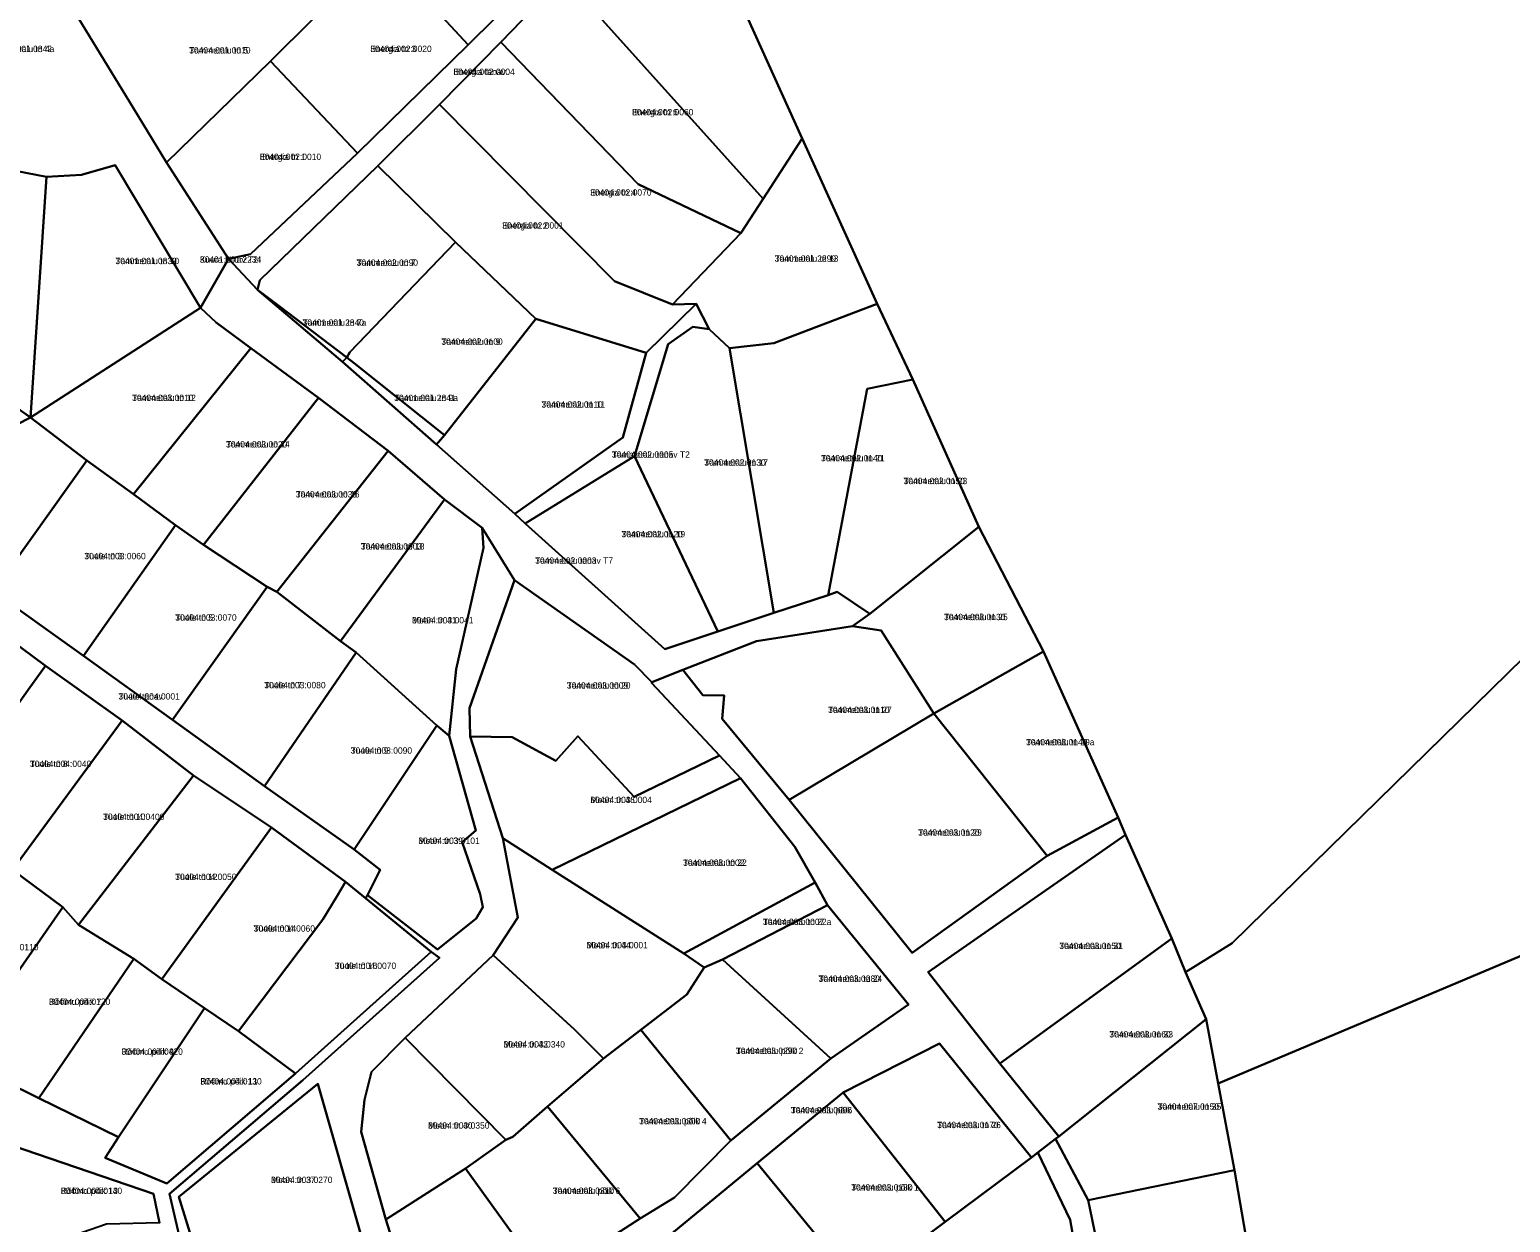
# Model space of a CAD drawing. Extents: x 542681 to 554572, y 6566489 to 6580482.
# Drawn here: x 544171.9 to 544521.7, y 6577252.9 to 6577534.7 of the extents above; entities that cross this region are included whole.
import ezdxf

# ---------------------------------------------------------------- set-up
doc = ezdxf.new("R2010")
doc.units = 0
for name, color, linetype in [('L_AADRESS', 7, 'Continuous'), ('PIIR', 7, 'Continuous'), ('TUNNUS', 7, 'Continuous')]:
    doc.layers.add(name, color=color, linetype=linetype)

msp = doc.modelspace()

# ---------------------------------------------------------------- linework, layer by layer
at = {"layer": 'PIIR'}
for points in [[(544449.83, 6577300.88), (544445, 6577312.02), (544455.98, 6577318.88), (544567.03, 6577427.6), (544592.49, 6577454.34), (544844.68, 6577695.48), (544856.46, 6577707.84), (544874.5, 6577712.66), (545014.95, 6577746.58), (545020.65, 6577747.95), (545024.76, 6577736.05), (545169.53, 6577765.79), (545193.94, 6577772.94), (545209.3, 6577776.23), (545215.43, 6577714.56), (545224.16, 6577610.98), (545218.92, 6577608.77), (544452.65, 6577285.75)], [(544456.52, 6577265.21), (544452.65, 6577285.75), (545218.92, 6577608.77), (545224.16, 6577610.98), (545231.09, 6577528.66), (545236.55, 6577455.03), (545231.68, 6577453.11), (544923.07, 6577331.26), (544475.6, 6577156.69), (544471.1, 6577182.9), (544466.29, 6577209.93), (544461.31, 6577237.31)], [(544323.78, 6577576.84), (544325.13, 6577573.79), (544298.11, 6577547.15), (544283.21, 6577531.68), (544268.74, 6577517), (544254.12, 6577502.47), (544226.23, 6577475.49), (544225.74, 6577473.24), (544218.85, 6577480.54), (544224.05, 6577481.6), (544249.34, 6577505.45), (544275.48, 6577531.05), (544300.6, 6577555.92)], [(544254.89, 6577553.3), (544276, 6577574.26), (544280.43, 6577578.31), (544300.6, 6577555.92), (544275.48, 6577531.05)], [(544325.13, 6577573.79), (544354.39, 6577508.96), (544345.19, 6577494.73), (544298.11, 6577547.15)], [(544181.54, 6577540.45), (544197.95, 6577540.09), (544224.95, 6577545.28), (544230.18, 6577546.68), (544241.63, 6577554.76), (544248.95, 6577547.27), (544228.78, 6577527.21), (544204.21, 6577503.3), (544196.49, 6577515.94)], [(544228.78, 6577527.21), (544248.95, 6577547.27), (544254.89, 6577553.3), (544275.48, 6577531.05), (544249.34, 6577505.45)], [(544298.11, 6577547.15), (544345.19, 6577494.73), (544339.87, 6577486.55), (544315.65, 6577498.13), (544283.21, 6577531.68)], [(544268.74, 6577517), (544283.21, 6577531.68), (544315.65, 6577498.13), (544339.87, 6577486.55), (544323.73, 6577469.72), (544310.09, 6577475.22)], [(544249.34, 6577505.45), (544224.05, 6577481.6), (544218.85, 6577480.54), (544204.21, 6577503.3), (544228.78, 6577527.21)], [(544268.74, 6577517), (544310.09, 6577475.22), (544323.73, 6577469.72), (544329.32, 6577469.91), (544317.57, 6577458.32), (544291.49, 6577466.39), (544272.51, 6577484.48), (544254.12, 6577502.47)], [(544329.32, 6577469.91), (544323.73, 6577469.72), (544339.87, 6577486.55), (544345.19, 6577494.73), (544354.39, 6577508.96), (544372.1, 6577469.9), (544347.68, 6577460.63), (544337.19, 6577459.45), (544332.42, 6577463.91)], [(544160.05, 6577504.83), (544168.56, 6577501.31), (544175.84, 6577499.89), (544172.06, 6577443.05), (544137.99, 6577467.25)], [(544175.84, 6577499.89), (544184.11, 6577500.33), (544192.06, 6577502.67), (544212.23, 6577468.98), (544172.06, 6577443.05)], [(544246.79, 6577457.22), (544230.76, 6577469.42), (544225.74, 6577473.24), (544226.23, 6577475.49), (544254.12, 6577502.47), (544272.51, 6577484.48), (544247.55, 6577458.46)], [(544247.55, 6577458.46), (544272.51, 6577484.48), (544291.49, 6577466.39), (544269.87, 6577438.87), (544248.51, 6577455.86), (544246.79, 6577457.22)], [(544212.23, 6577468.98), (544218.85, 6577480.54), (544225.74, 6577473.24), (544245.79, 6577456.17), (544268.03, 6577436.65), (544286.48, 6577420.3), (544288.91, 6577417.97), (544321.98, 6577388.31), (544334.48, 6577392.49), (544347.72, 6577396.91), (544360.54, 6577401.06), (544362.7, 6577401.87), (544370.39, 6577396.67), (544366.25, 6577393.73), (544343.62, 6577390.19), (544326.16, 6577383.41), (544318.9, 6577380.55), (544314.8, 6577384.68), (544286.4, 6577404.61), (544278.8, 6577416.98), (544269.91, 6577423.64), (544256.55, 6577435.18), (544240.13, 6577447.69), (544224.11, 6577459.45), (544215.91, 6577465.49)], [(544245.79, 6577456.17), (544225.74, 6577473.24), (544230.76, 6577469.42), (544246.79, 6577457.22)], [(544137.99, 6577467.25), (544172.06, 6577443.05), (544133.57, 6577423.36), (544115.96, 6577438)], [(544185.38, 6577432.88), (544172.06, 6577443.05), (544212.23, 6577468.98), (544215.91, 6577465.49), (544224.11, 6577459.45), (544196.38, 6577424.9)], [(544286.48, 6577420.3), (544312.02, 6577438.31), (544317.57, 6577458.32), (544329.32, 6577469.91), (544332.42, 6577463.91), (544328.56, 6577464.48), (544322.76, 6577460.38), (544314.81, 6577433.87), (544288.91, 6577417.97)], [(544337.19, 6577459.45), (544347.68, 6577460.63), (544372.1, 6577469.9), (544380.51, 6577452.04), (544369.72, 6577449.78), (544360.54, 6577401.06), (544347.72, 6577396.91)], [(544268.03, 6577436.65), (544269.87, 6577438.87), (544291.49, 6577466.39), (544317.57, 6577458.32), (544312.02, 6577438.31), (544286.48, 6577420.3)], [(544322.76, 6577460.38), (544328.56, 6577464.48), (544332.42, 6577463.91), (544337.19, 6577459.45), (544347.72, 6577396.91), (544334.48, 6577392.49), (544314.81, 6577433.87)], [(544206.32, 6577417.64), (544196.38, 6577424.9), (544224.11, 6577459.45), (544240.13, 6577447.69), (544212.96, 6577413)], [(544268.03, 6577436.65), (544245.79, 6577456.17), (544246.79, 6577457.22), (544248.51, 6577455.86), (544269.87, 6577438.87)], [(544362.7, 6577401.87), (544360.54, 6577401.06), (544369.72, 6577449.78), (544380.51, 6577452.04), (544396.15, 6577417.22), (544370.39, 6577396.67)], [(544227.96, 6577403.08), (544212.96, 6577413), (544240.13, 6577447.69), (544256.55, 6577435.18), (544230.31, 6577401.83)], [(544163.25, 6577401.97), (544133.57, 6577423.36), (544172.06, 6577443.05), (544185.38, 6577432.88)], [(544256.55, 6577435.18), (544269.91, 6577423.64), (544245.33, 6577390.23), (544230.31, 6577401.83)], [(544163.25, 6577401.97), (544185.38, 6577432.88), (544196.38, 6577424.9), (544206.32, 6577417.64), (544184.57, 6577386.76)], [(544314.81, 6577433.87), (544334.48, 6577392.49), (544321.98, 6577388.31), (544288.91, 6577417.97)], [(544133.57, 6577423.36), (544163.25, 6577401.97), (544184.57, 6577386.76), (544205.61, 6577371.6), (544227.39, 6577355.94), (544248.54, 6577340.99), (544254.71, 6577336.16), (544251.67, 6577330.24), (544251.2, 6577329.49), (544246.47, 6577333.34), (544229.05, 6577346.22), (544210.56, 6577358.48), (544193.75, 6577371.48), (544175.61, 6577384.37), (544158.34, 6577397.13), (544140.43, 6577410.12), (544126.41, 6577420.01)], [(544269.91, 6577423.64), (544278.8, 6577416.98), (544279.13, 6577412.26), (544272.67, 6577383.58), (544271.02, 6577367.81), (544268.08, 6577370.32), (544249, 6577387.53), (544245.33, 6577390.23)], [(544184.57, 6577386.76), (544206.32, 6577417.64), (544212.96, 6577413), (544227.96, 6577403.08), (544205.61, 6577371.6)], [(544373.04, 6577392.73), (544366.25, 6577393.73), (544370.39, 6577396.67), (544396.15, 6577417.22), (544411.39, 6577387.74), (544385.5, 6577373.12)], [(544286.4, 6577404.61), (544314.8, 6577384.68), (544318.9, 6577380.55), (544318.91, 6577380.32), (544334.84, 6577363.22), (544314.71, 6577353.4), (544301.36, 6577367.73), (544296.23, 6577361.94), (544285.89, 6577367.56), (544275.95, 6577367.65), (544275.81, 6577374.35)], [(544205.61, 6577371.6), (544227.96, 6577403.08), (544230.31, 6577401.83), (544245.33, 6577390.23), (544249, 6577387.53), (544227.39, 6577355.94)], [(544150.11, 6577348.83), (544145.33, 6577352.28), (544132.12, 6577361.35), (544158.34, 6577397.13), (544175.61, 6577384.37), (544171.94, 6577379.25), (544163.79, 6577367.89), (544156.39, 6577357.58), (544150.65, 6577349.58)], [(544335.47, 6577371.87), (544335.99, 6577377.35), (544330.94, 6577377.44), (544326.16, 6577383.41), (544343.62, 6577390.19), (544366.25, 6577393.73), (544373.04, 6577392.73), (544385.5, 6577373.12), (544351.32, 6577352.72)], [(544227.39, 6577355.94), (544249, 6577387.53), (544268.08, 6577370.32), (544248.54, 6577340.99)], [(544411.39, 6577387.74), (544429.07, 6577348.58), (544412.29, 6577339.52), (544385.5, 6577373.12)], [(544162.15, 6577340.2), (544150.11, 6577348.83), (544150.65, 6577349.58), (544156.39, 6577357.58), (544163.79, 6577367.89), (544171.94, 6577379.25), (544175.61, 6577384.37), (544193.75, 6577371.48), (544167.85, 6577336.16)], [(544351.32, 6577352.72), (544385.5, 6577373.12), (544412.29, 6577339.52), (544380.39, 6577316.59)], [(544179.67, 6577327.41), (544167.85, 6577336.16), (544193.75, 6577371.48), (544210.56, 6577358.48), (544183.44, 6577323.16)], [(544254.71, 6577336.16), (544248.54, 6577340.99), (544268.08, 6577370.32), (544271.02, 6577367.81), (544277.26, 6577345.47), (544274.04, 6577342.71), (544278.28, 6577330.47), (544278.91, 6577327.41), (544277.33, 6577324.68), (544268.2, 6577317.37), (544251.67, 6577330.24)], [(544334.84, 6577363.22), (544339.83, 6577357.86), (544295.34, 6577336.18), (544283.69, 6577343.68), (544275.95, 6577367.65), (544285.89, 6577367.56), (544296.23, 6577361.94), (544301.36, 6577367.73), (544314.71, 6577353.4)], [(544196.46, 6577315.15), (544183.44, 6577323.16), (544210.56, 6577358.48), (544229.05, 6577346.22), (544203.1, 6577310.37)], [(544339.83, 6577357.86), (544352.68, 6577341.61), (544357.45, 6577333.16), (544326.4, 6577316.4), (544295.34, 6577336.18)], [(544213.15, 6577303.51), (544203.1, 6577310.37), (544229.05, 6577346.22), (544246.47, 6577333.34), (544244.42, 6577329.91), (544241.13, 6577324.44), (544221.19, 6577298.09)], [(544384.13, 6577312.03), (544430.75, 6577344.46), (544441.76, 6577319.94), (544401.08, 6577290.48)], [(544326.4, 6577316.4), (544331.24, 6577313.15), (544327.13, 6577306.75), (544316.3, 6577298.4), (544307.45, 6577291.61), (544300.63, 6577298.49), (544281.38, 6577316.06), (544287.23, 6577324.91), (544283.69, 6577343.68), (544295.34, 6577336.18)], [(544139.24, 6577305.35), (544162.15, 6577340.2), (544167.85, 6577336.16), (544179.67, 6577327.41), (544156.41, 6577293.87)], [(544221.19, 6577298.09), (544241.13, 6577324.44), (544244.42, 6577329.91), (544246.47, 6577333.34), (544251.2, 6577329.49), (544266.75, 6577316.83), (544234.69, 6577288.08)], [(544357.45, 6577333.16), (544360.4, 6577327.83), (544335.56, 6577315.04), (544331.24, 6577313.15), (544326.4, 6577316.4)], [(544157.1, 6577290.6), (544157.23, 6577292.89), (544156.41, 6577293.87), (544179.67, 6577327.41), (544183.44, 6577323.16), (544196.46, 6577315.15), (544174, 6577282.28)], [(544360.4, 6577327.83), (544379.49, 6577304.4), (544361.18, 6577291.63), (544335.56, 6577315.04)], [(544401.08, 6577290.48), (544441.76, 6577319.94), (544445, 6577312.02), (544449.83, 6577300.88), (544415.01, 6577273.23)], [(544196.46, 6577315.15), (544203.1, 6577310.37), (544213.15, 6577303.51), (544192.88, 6577273), (544174, 6577282.28)], [(544260.56, 6577296.5), (544281.38, 6577316.06), (544300.63, 6577298.49), (544307.45, 6577291.61), (544294.22, 6577280.25), (544286, 6577273.11), (544284.39, 6577272.38)], [(544316.3, 6577298.4), (544327.13, 6577306.75), (544331.24, 6577313.15), (544335.56, 6577315.04), (544361.18, 6577291.63), (544337.52, 6577272.23)], [(544189.72, 6577268.16), (544192.88, 6577273), (544213.15, 6577303.51), (544221.19, 6577298.09), (544234.69, 6577288.08), (544204.26, 6577262.08)], [(544456.52, 6577265.21), (544421.97, 6577258.14), (544414.23, 6577272.62), (544415.01, 6577273.23), (544449.83, 6577300.88), (544452.65, 6577285.75)], [(544250.2, 6577274.26), (544250.99, 6577281.84), (544252.62, 6577288.49), (544260.56, 6577296.5), (544284.39, 6577272.38), (544274.81, 6577265.67), (544256.03, 6577253.6)], [(544294.22, 6577280.25), (544307.45, 6577291.61), (544316.3, 6577298.4), (544337.52, 6577272.23), (544324.24, 6577258.77), (544316.1, 6577253.81)], [(544386.86, 6577295.18), (544408.54, 6577268.25), (544388.19, 6577253.04), (544364.05, 6577283.62)], [(544207.14, 6577258.94), (544239.96, 6577285.6), (544250.31, 6577249.52), (544213.36, 6577238.8)], [(544364.05, 6577283.62), (544388.19, 6577253.04), (544381.63, 6577248.14), (544368.3, 6577236.86), (544343.79, 6577266.92)], [(544274.81, 6577265.67), (544284.39, 6577272.38), (544286, 6577273.11), (544294.22, 6577280.25), (544316.1, 6577253.81), (544293.74, 6577239.41)], [(544152.26, 6577276.33), (544201.13, 6577259.66), (544202.58, 6577252.78), (544190.01, 6577252.52), (544162.33, 6577242.91)], [(544417.71, 6577253.54), (544425.07, 6577211.96), (544390.19, 6577205.83), (544387.14, 6577231.76), (544381.63, 6577248.14), (544388.19, 6577253.04), (544408.54, 6577268.25), (544410.06, 6577269.38)], [(544266.26, 6577223.12), (544264.6, 6577226.38), (544256.03, 6577253.6), (544274.81, 6577265.67), (544293.74, 6577239.41), (544269.36, 6577223.2)], [(544343.79, 6577266.92), (544368.3, 6577236.86), (544349.57, 6577221.02), (544323.61, 6577250.29)], [(544461.31, 6577237.31), (544427.37, 6577231.84), (544421.97, 6577258.14), (544456.52, 6577265.21)]]:
    msp.add_lwpolyline(points, close=True, dxfattribs=at)
for points in [[(544844.68, 6577695.48), (544592.49, 6577454.34), (544567.03, 6577427.6), (544455.98, 6577318.88), (544445, 6577312.02), (544441.76, 6577319.94), (544430.75, 6577344.46), (544429.07, 6577348.58), (544411.39, 6577387.74), (544396.15, 6577417.22), (544380.51, 6577452.04), (544372.1, 6577469.9), (544354.39, 6577508.96), (544325.13, 6577573.79)], [(544181.54, 6577540.45), (544196.49, 6577515.94), (544204.21, 6577503.3), (544218.85, 6577480.54), (544212.23, 6577468.98), (544192.06, 6577502.67), (544184.11, 6577500.33), (544175.84, 6577499.89), (544168.56, 6577501.31)], [(544211.25, 6577232.37), (544204.94, 6577259.69), (544236.43, 6577286.48), (544268.68, 6577315.41), (544266.75, 6577316.83), (544251.2, 6577329.49), (544251.67, 6577330.24), (544268.2, 6577317.37), (544277.33, 6577324.68), (544278.91, 6577327.41), (544278.28, 6577330.47), (544274.04, 6577342.71), (544277.26, 6577345.47), (544271.02, 6577367.81), (544272.67, 6577383.58), (544279.13, 6577412.26), (544278.8, 6577416.98), (544286.4, 6577404.61), (544275.81, 6577374.35), (544275.95, 6577367.65), (544283.69, 6577343.68), (544287.23, 6577324.91), (544281.38, 6577316.06), (544260.56, 6577296.5), (544252.62, 6577288.49), (544250.99, 6577281.84), (544250.2, 6577274.26), (544256.03, 6577253.6), (544264.6, 6577226.38)], [(544293.74, 6577239.41), (544316.1, 6577253.81), (544324.24, 6577258.77), (544337.52, 6577272.23), (544361.18, 6577291.63), (544379.49, 6577304.4), (544360.4, 6577327.83), (544357.45, 6577333.16), (544352.68, 6577341.61), (544339.83, 6577357.86), (544334.84, 6577363.22), (544318.91, 6577380.32), (544318.9, 6577380.55), (544326.16, 6577383.41), (544330.94, 6577377.44), (544335.99, 6577377.35), (544335.47, 6577371.87), (544351.32, 6577352.72), (544380.39, 6577316.59), (544412.29, 6577339.52), (544429.07, 6577348.58), (544430.75, 6577344.46), (544384.13, 6577312.03), (544401.08, 6577290.48), (544415.01, 6577273.23), (544414.23, 6577272.62), (544410.06, 6577269.38), (544408.54, 6577268.25), (544386.86, 6577295.18), (544364.05, 6577283.62), (544343.79, 6577266.92), (544323.61, 6577250.29)], [(544157.1, 6577290.6), (544174, 6577282.28), (544192.88, 6577273), (544189.72, 6577268.16), (544204.26, 6577262.08), (544234.69, 6577288.08), (544266.75, 6577316.83), (544268.68, 6577315.41), (544236.43, 6577286.48), (544204.94, 6577259.69), (544211.25, 6577232.37)], [(544250.31, 6577249.52), (544239.96, 6577285.6), (544207.14, 6577258.94), (544213.36, 6577238.8)], [(544202.58, 6577252.78), (544201.13, 6577259.66), (544152.26, 6577276.33), (544162.33, 6577242.91)], [(544425.07, 6577211.96), (544417.71, 6577253.54), (544410.06, 6577269.38), (544414.23, 6577272.62), (544421.97, 6577258.14), (544427.37, 6577231.84)]]:
    msp.add_lwpolyline(points, dxfattribs=at)

# ---------------------------------------------------------------- texts
at = {"layer": 'L_AADRESS'}
for s, p in [('Tammetalu tn 4a', (544162.65, 6577529.36)), ('Tammetalu tn 5', (544209.56, 6577529.03)), ('Energia tn 3', (544252.36, 6577529.38)), ('Energia tänav', (544271.99, 6577523.96)), ('Energia tn 6', (544314.2, 6577514.43)), ('Energia tn 1', (544226.24, 6577503.88)), ('Energia tn 4', (544304.3, 6577495.46)), ('Energia tn 2', (544283.52, 6577487.66)), ('Tammetalu tn 10', (544192.14, 6577479.27)), ('Kuura tänav T2', (544212.09, 6577479.6)), ('Tammetalu tn 13', (544347.91, 6577479.83)), ('Tammetalu tn 7', (544249.12, 6577478.87)), ('Tammetalu tn 7a', (544236.36, 6577464.71)), ('Tammetalu tn 9', (544269.14, 6577460.21)), ('Tammetalu tn 12', (544196.08, 6577446.94)), ('Tammetalu tn 9a', (544258.02, 6577446.93)), ('Tammetalu tn 11', (544292.8, 6577445.37)), ('Tammetalu tn 14', (544218.26, 6577435.96)), ('Tammetalu tänav T2', (544309.45, 6577433.54)), ('Tammetalu tn 17', (544331.27, 6577431.67)), ('Tammetalu tn 21', (544358.85, 6577432.69)), ('Tammetalu tn 23', (544378.34, 6577427.3)), ('Tammetalu tn 16', (544234.75, 6577424.15)), ('Tammetalu tn 19', (544311.69, 6577414.75)), ('Tuule tn 3', (544184.79, 6577409.56)), ('Tammetalu tn 18', (544250.11, 6577411.86)), ('Tammetalu tänav T7', (544291.31, 6577408.49)), ('Tuule tn 5', (544206.27, 6577395.04)), ('Tammetalu tn 25', (544387.91, 6577395.17)), ('Mooni tn 41', (544262.23, 6577394.4)), ('Tuule tn 7', (544227.3, 6577379.08)), ('Tammetalu tn 20', (544298.79, 6577379)), ('Tuule tänav', (544192.85, 6577376.42)), ('Tammetalu tn 27', (544360.52, 6577373.23)), ('Tuule tn 9', (544247.73, 6577363.62)), ('Tammetalu tn 29a', (544407.29, 6577365.61)), ('Tuule tn 8', (544171.93, 6577360.48)), ('Mooni tn 46', (544304.37, 6577351.96)), ('Tuule tn 10', (544189.21, 6577347.98)), ('Tammetalu tn 29', (544381.8, 6577344.26)), ('Mooni tn 39', (544263.72, 6577342.32)), ('Tammetalu tn 22', (544326.25, 6577337.13)), ('Tuule tn 12', (544206.24, 6577333.79)), ('Tuule tn 14', (544224.79, 6577321.58)), ('Tammetalu tn 22a', (544345.12, 6577323.15)), ('Mooni tn 44', (544303.44, 6577317.65)), ('Tammetalu tn 31', (544415.15, 6577317.47)), ('Tuule tn 16', (544243.97, 6577312.78)), ('Tammetalu tn 24', (544358.26, 6577309.73)), ('Rõõmu põik 7', (544176.43, 6577304.29)), ('Mooni tn 42', (544283.84, 6577294.22)), ('Tammetalu tn 33', (544426.97, 6577296.59)), ('Rõõmu põik 9', (544193.57, 6577292.49)), ('Tammetalu põik 2', (544338.74, 6577292.68)), ('Rõõmu põik 11', (544212.2, 6577285.48)), ('Tammetalu põik 4', (544315.87, 6577276.08)), ('Tammetalu põik', (544351.72, 6577278.68)), ('Tammetalu tn 35', (544438.37, 6577279.51)), ('Mooni tn 40', (544266.02, 6577275.05)), ('Tammetalu tn 26', (544386.29, 6577275.17)), ('Mooni tn 37', (544228.91, 6577262.2)), ('Rõõmu põik 13', (544179.22, 6577259.62)), ('Tammetalu põik 6', (544295.46, 6577259.64)), ('Tammetalu põik 1', (544365.99, 6577260.43))]:
    msp.add_text(s, height=1.5, dxfattribs=at).set_placement(p)
at = {"layer": 'TUNNUS'}
for s, p in [('30401:001:0842', (544162.65, 6577529.36)), ('30404:001:0010', (544209.56, 6577529.03)), ('30404:002:0020', (544252.36, 6577529.38)), ('30404:002:0004', (544271.99, 6577523.96)), ('30404:002:0060', (544314.2, 6577514.43)), ('30404:002:0010', (544226.24, 6577503.88)), ('30404:002:0070', (544304.3, 6577495.46)), ('30404:002:0001', (544283.52, 6577487.66)), ('30401:001:0839', (544192.14, 6577479.27)), ('30401:001:2234', (544212.09, 6577479.6)), ('30401:001:2299', (544347.91, 6577479.83)), ('30404:002:0090', (544249.12, 6577478.87)), ('30401:001:2840', (544236.36, 6577464.71)), ('30404:002:0100', (544269.14, 6577460.21)), ('30404:003:0010', (544196.08, 6577446.94)), ('30401:001:2841', (544258.02, 6577446.93)), ('30404:002:0110', (544292.8, 6577445.37)), ('30404:003:0020', (544218.26, 6577435.96)), ('30404:002:0005', (544309.45, 6577433.54)), ('30404:002:0130', (544331.27, 6577431.67)), ('30404:002:0140', (544358.85, 6577432.69)), ('30404:002:0150', (544378.34, 6577427.3)), ('30404:003:0030', (544234.75, 6577424.15)), ('30404:002:0120', (544311.69, 6577414.75)), ('30404:003:0060', (544184.79, 6577409.56)), ('30404:003:0003', (544250.11, 6577411.86)), ('30404:002:0003', (544291.31, 6577408.49)), ('30404:003:0130', (544387.91, 6577395.17)), ('30404:003:0070', (544206.27, 6577395.04)), ('30404:003:0041', (544262.23, 6577394.4)), ('30404:003:0080', (544227.3, 6577379.08)), ('30404:003:0009', (544298.79, 6577379)), ('30404:004:0001', (544192.85, 6577376.42)), ('30404:003:0110', (544360.52, 6577373.23)), ('30404:003:0090', (544247.73, 6577363.62)), ('30404:003:0140', (544407.29, 6577365.61)), ('30404:004:0040', (544171.93, 6577360.48)), ('30404:003:0004', (544304.37, 6577351.96)), ('30404:004:0400', (544189.21, 6577347.98)), ('30404:003:0120', (544381.8, 6577344.26)), ('30404:003:0101', (544263.72, 6577342.32)), ('30404:003:0002', (544326.25, 6577337.13)), ('30404:004:0050', (544206.24, 6577333.79)), ('30404:004:0060', (544224.79, 6577321.58)), ('30404:003:0007', (544345.12, 6577323.15)), ('30404:004:0110', (544159.46, 6577317.18)), ('30404:003:0001', (544303.44, 6577317.65)), ('30404:003:0150', (544415.15, 6577317.47)), ('30404:004:0070', (544243.97, 6577312.78)), ('30404:003:0280', (544358.26, 6577309.73)), ('30404:004:0120', (544176.43, 6577304.29)), ('30404:003:0340', (544283.84, 6577294.22)), ('30404:003:0160', (544426.97, 6577296.59)), ('30404:004:0420', (544193.57, 6577292.49)), ('30404:003:0290', (544338.74, 6577292.68)), ('30404:004:0130', (544212.2, 6577285.48)), ('30404:003:0006', (544351.72, 6577278.68)), ('30404:007:0150', (544438.37, 6577279.51)), ('30404:003:0350', (544266.02, 6577275.05)), ('30404:003:0300', (544315.87, 6577276.08)), ('30404:003:0170', (544386.29, 6577275.17)), ('30404:003:0270', (544228.91, 6577262.2)), ('30404:004:0140', (544179.22, 6577259.62)), ('30404:003:0310', (544295.46, 6577259.64)), ('30404:003:0180', (544365.99, 6577260.43))]:
    msp.add_text(s, height=1.5, dxfattribs=at).set_placement(p)

doc.saveas('drawing.dxf')
